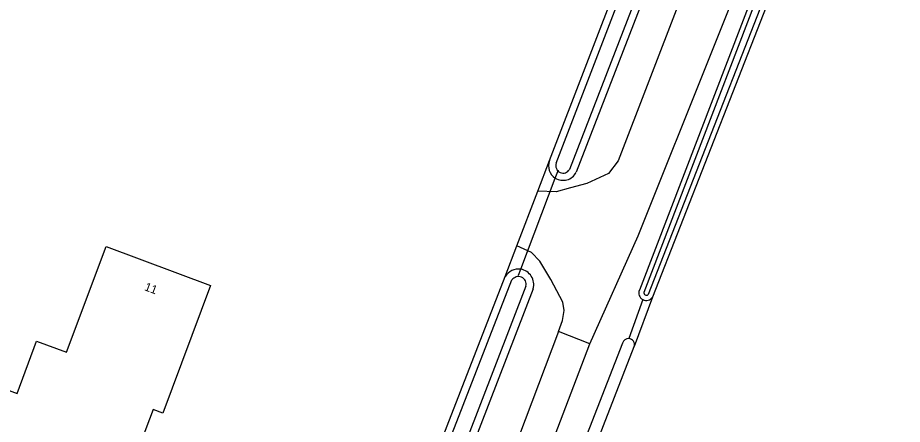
# Model space of a CAD drawing. Extents: x 155209 to 156823, y 385356 to 388482.
# Drawn here: x 155769.5 to 155874.2, y 386567.5 to 386615.6 of the extents above; entities that cross this region are included whole.
import ezdxf

# ---------------------------------------------------------------- set-up
doc = ezdxf.new("R2010")
doc.units = 0
for name, color, linetype in [('IMGEO_Bouwland', 7, 'Continuous'), ('IMGEO_Duiker', 7, 'Continuous'), ('IMGEO_Erf', 7, 'Continuous'), ('IMGEO_Grasland_overig', 7, 'Continuous'), ('IMGEO_Groenvoorziening', 7, 'Continuous'), ('IMGEO_Loofbos', 7, 'Continuous'), ('IMGEO_Pand', 7, 'Continuous'), ('IMGEO_Pand_nummerreeks', 7, 'Continuous'), ('IMGEO_Rijbaan_lokaal_onverhard', 7, 'Continuous'), ('IMGEO_Rijbaan_lokaal_open', 7, 'Continuous'), ('IMGEO_Waterloop', 7, 'Continuous')]:
    doc.layers.add(name, color=color, linetype=linetype)

msp = doc.modelspace()

# ---------------------------------------------------------------- linework, layer by layer
at = {"layer": 'IMGEO_Bouwland'}
msp.add_lwpolyline([(155864.34, 386632.76), (155844.68, 386582.56)], dxfattribs=at)
at = {"layer": 'IMGEO_Duiker'}
for points in [[(155828.8, 386585.14), (155829.07, 386585.85), (155833.17, 386596.64), (155833.53, 386597.6)], [(155843.52, 386582.27), (155841.88, 386577.65)]]:
    msp.add_lwpolyline(points, dxfattribs=at)
at = {"layer": 'IMGEO_Erf'}
for points in [[(155832.48, 386598.7), (155858.39, 386666.09)], [(155769.48, 386436.4), (155794.21, 386500), (155827.24, 386584.98)]]:
    msp.add_lwpolyline(points, dxfattribs=at)
at = {"layer": 'IMGEO_Grasland_overig'}
for points in [[(155862.38, 386633.54), (155843.12, 386583.39)], [(155844.68, 386582.56), (155842.49, 386576.7)]]:
    msp.add_lwpolyline(points, dxfattribs=at)
for radius, start, end in [(0.887, 157.1718, 241.7029), (0.886, 241.6544, 326.2784)]:
    msp.add_arc((155843.94, 386583.05), radius, start, end, dxfattribs=at)
at = {"layer": 'IMGEO_Groenvoorziening'}
for points in [[(155861.84, 386664.97), (155835.62, 386597.32)], [(155831.1, 386595.08), (155832.48, 386598.7)]]:
    msp.add_lwpolyline(points, dxfattribs=at)
for start, end in [(159.3186, 237.4844), (237.5754, 333.0217)]:
    msp.add_arc((155834.09, 386598.09), 1.72, start, end, dxfattribs=at)
at = {"layer": 'IMGEO_Loofbos'}
for points in [[(155827.24, 386584.98), (155828.63, 386588.62)], [(155830.54, 386583.55), (155798.32, 386500), (155773.25, 386434.99)]]:
    msp.add_lwpolyline(points, dxfattribs=at)
for start, end in [(81.3767, 149.2995), (343.8217, 81.2949)]:
    msp.add_arc((155828.8, 386584.05), 1.81, start, end, dxfattribs=at)
at = {"layer": 'IMGEO_Pand'}
msp.add_lwpolyline([(155759.25, 386561.86), (155760.53, 386565.29), (155758.67, 386565.98), (155761.68, 386574.04), (155769.44, 386571.14), (155771.76, 386577.35), (155775.31, 386576.02), (155780, 386588.55), (155792.35, 386583.93), (155786.69, 386568.83), (155785.55, 386569.26), (155784.14, 386565.5), (155791.95, 386562.57), (155789.02, 386554.73), (155768.53, 386562.4), (155767.21, 386558.86), (155806.34, 386544.21), (155789.79, 386500), (155774.62, 386459.47), (155689.46, 386491.38), (155692.69, 386500), (155721.18, 386576.11), (155759.25, 386561.86)], dxfattribs=at)
at = {"layer": 'IMGEO_Rijbaan_lokaal_onverhard'}
for points in [[(155833.54, 386578.47), (155803.9, 386500), (155778.59, 386432.99)], [(155770.07, 386419.5), (155764.64, 386405.34), (155770.92, 386403.12), (155780.04, 386426.8), (155807.91, 386500), (155837.24, 386577.02)]]:
    msp.add_lwpolyline(points, dxfattribs=at)
at = {"layer": 'IMGEO_Rijbaan_lokaal_open'}
for points in [[(155855.14, 386636.42), (155840.59, 386598.69), (155839.46, 386597.18), (155836.9, 386595.99), (155834.97, 386595.48), (155833.27, 386595.02), (155831.1, 386595.08)], [(155837.24, 386577.02), (155842.99, 386589.8), (155860.74, 386634.19)], [(155828.63, 386588.62), (155831.1, 386595.08)], [(155833.54, 386578.47), (155834.03, 386579.78), (155834.21, 386580.97), (155834.05, 386581.94), (155832.62, 386584.62), (155831.32, 386586.8), (155830.35, 386587.85), (155828.63, 386588.62)], [(155837.24, 386577.02), (155833.54, 386578.47)]]:
    msp.add_lwpolyline(points, dxfattribs=at)
at = {"layer": 'IMGEO_Waterloop'}
for points in [[(155833.28, 386598.4), (155859.19, 386665.79)], [(155861.03, 386665.24), (155834.84, 386597.67)], [(155843.67, 386583.14), (155862.92, 386633.26), (155862.93, 386633.28), (155862.93, 386633.29), (155862.94, 386633.31), (155862.98, 386633.39), (155863, 386633.47), (155863.03, 386633.55), (155873.19, 386660.57)], [(155874.25, 386660.14), (155863.79, 386632.98), (155844.15, 386582.85)], [(155770.33, 386436.1), (155795.04, 386499.68), (155828.04, 386584.58)], [(155829.69, 386583.83), (155797.49, 386500.32), (155772.43, 386435.33)], [(155841.12, 386577.09), (155811.05, 386500), (155806.67, 386488.75)], [(155808.11, 386488.2), (155812.69, 386500), (155842.49, 386576.7)]]:
    msp.add_lwpolyline(points, dxfattribs=at)
for centre, radius, start, end in [((155834.09, 386598.09), 0.864, 159.3832, 330.7276), ((155828.8, 386584.06), 0.921, 345.7483, 145.6148), ((155843.94, 386583.05), 0.289, 160.7637, 316.7521), ((155841.82, 386576.93), 0.716, 84.7897, 167.274), ((155841.81, 386576.93), 0.719, 341.1196, 84.5705)]:
    msp.add_arc(centre, radius, start, end, dxfattribs=at)

# ---------------------------------------------------------------- texts
at = {"layer": 'IMGEO_Pand_nummerreeks'}
msp.add_text('11', height=1, rotation=339.4791, dxfattribs=at).set_placement((155784.44, 386583.39))

doc.saveas('drawing.dxf')
